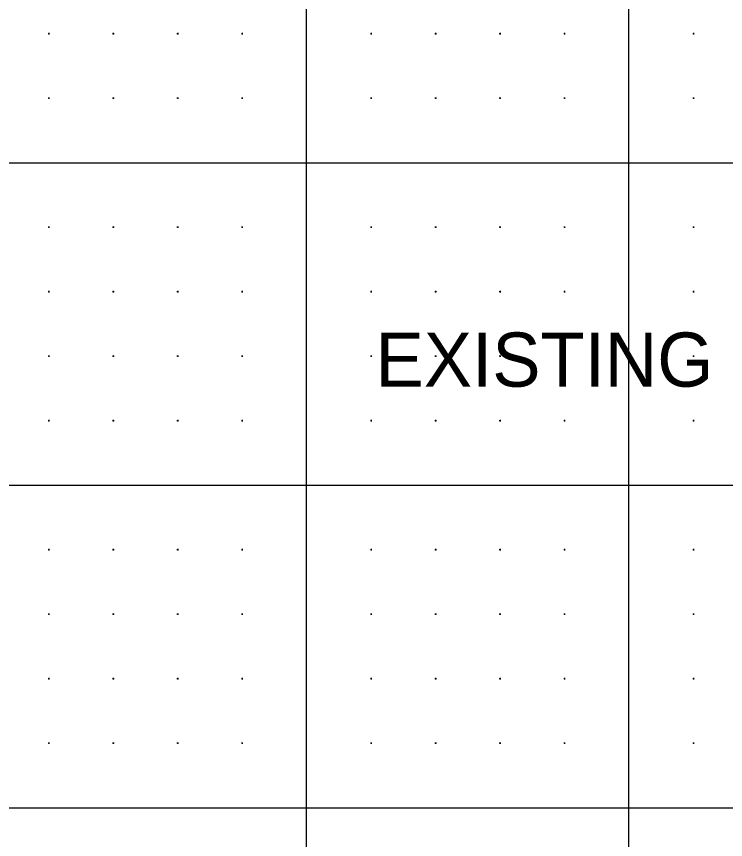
# Model space of a CAD drawing. Extents: x 471 to 2121, y 140 to 650.
# Drawn here: x 691 to 801, y 395.1 to 522.7 of the extents above; entities that cross this region are included whole.
import ezdxf

# ---------------------------------------------------------------- set-up
doc = ezdxf.new("R2010")
doc.units = 0
doc.layers.add('Default', color=7, linetype='Continuous')
doc.layers.add('DSN_DRFT_Border Grid', color=7, linetype='Continuous')

msp = doc.modelspace()

# ---------------------------------------------------------------- linework, layer by layer
at = {"layer": 'DSN_DRFT_Border Grid'}
for p, q in [((736.06, 150), (736.06, 650)), ((736.06, 150), (736.06, 650)), ((786.06, 150), (786.06, 650)), ((786.06, 150), (786.06, 650)), ((696.18, 520), (695.94, 520)), ((696.18, 520), (695.94, 520)), ((696.06, 520.12), (696.06, 519.88)), ((696.06, 520.12), (696.06, 519.88)), ((706.18, 520), (705.94, 520)), ((706.18, 520), (705.94, 520)), ((706.06, 520.12), (706.06, 519.88)), ((706.06, 520.12), (706.06, 519.88)), ((716.18, 520), (715.94, 520)), ((716.18, 520), (715.94, 520)), ((716.06, 520.12), (716.06, 519.88)), ((716.06, 520.12), (716.06, 519.88)), ((726.18, 520), (725.94, 520)), ((726.18, 520), (725.94, 520)), ((726.06, 520.12), (726.06, 519.88)), ((726.06, 520.12), (726.06, 519.88)), ((746.18, 520), (745.94, 520)), ((746.18, 520), (745.94, 520)), ((746.06, 520.12), (746.06, 519.88)), ((746.06, 520.12), (746.06, 519.88)), ((756.18, 520), (755.94, 520)), ((756.18, 520), (755.94, 520)), ((756.06, 520.12), (756.06, 519.88)), ((756.06, 520.12), (756.06, 519.88)), ((766.18, 520), (765.94, 520)), ((766.18, 520), (765.94, 520)), ((766.06, 520.12), (766.06, 519.88)), ((766.06, 520.12), (766.06, 519.88)), ((776.18, 520), (775.94, 520)), ((776.18, 520), (775.94, 520)), ((776.06, 520.12), (776.06, 519.88)), ((776.06, 520.12), (776.06, 519.88)), ((796.18, 520), (795.94, 520)), ((796.18, 520), (795.94, 520)), ((796.06, 520.12), (796.06, 519.88)), ((796.06, 520.12), (796.06, 519.88)), ((696.18, 510), (695.94, 510)), ((696.18, 510), (695.94, 510)), ((696.06, 510.12), (696.06, 509.88)), ((696.06, 510.12), (696.06, 509.88)), ((706.18, 510), (705.94, 510)), ((706.18, 510), (705.94, 510)), ((706.06, 510.12), (706.06, 509.88)), ((706.06, 510.12), (706.06, 509.88)), ((716.18, 510), (715.94, 510)), ((716.18, 510), (715.94, 510)), ((716.06, 510.12), (716.06, 509.88)), ((716.06, 510.12), (716.06, 509.88)), ((726.18, 510), (725.94, 510)), ((726.18, 510), (725.94, 510)), ((726.06, 510.12), (726.06, 509.88)), ((726.06, 510.12), (726.06, 509.88)), ((746.18, 510), (745.94, 510)), ((746.18, 510), (745.94, 510)), ((746.06, 510.12), (746.06, 509.88)), ((746.06, 510.12), (746.06, 509.88)), ((756.18, 510), (755.94, 510)), ((756.18, 510), (755.94, 510)), ((756.06, 510.12), (756.06, 509.88)), ((756.06, 510.12), (756.06, 509.88)), ((766.18, 510), (765.94, 510)), ((766.18, 510), (765.94, 510)), ((766.06, 510.12), (766.06, 509.88)), ((766.06, 510.12), (766.06, 509.88)), ((776.18, 510), (775.94, 510)), ((776.18, 510), (775.94, 510)), ((776.06, 510.12), (776.06, 509.88)), ((776.06, 510.12), (776.06, 509.88)), ((796.18, 510), (795.94, 510)), ((796.18, 510), (795.94, 510)), ((796.06, 510.12), (796.06, 509.88)), ((796.06, 510.12), (796.06, 509.88)), ((521.06, 500), (2071.06, 500)), ((521.06, 500), (2071.06, 500)), ((696.06, 490.12), (696.06, 489.88)), ((696.06, 490.12), (696.06, 489.88)), ((706.06, 490.12), (706.06, 489.88)), ((706.06, 490.12), (706.06, 489.88)), ((716.06, 490.12), (716.06, 489.88)), ((716.06, 490.12), (716.06, 489.88)), ((726.06, 490.12), (726.06, 489.88)), ((726.06, 490.12), (726.06, 489.88)), ((746.06, 490.12), (746.06, 489.88)), ((746.06, 490.12), (746.06, 489.88)), ((756.06, 490.12), (756.06, 489.88)), ((756.06, 490.12), (756.06, 489.88)), ((766.06, 490.12), (766.06, 489.88)), ((766.06, 490.12), (766.06, 489.88)), ((776.06, 490.12), (776.06, 489.88)), ((776.06, 490.12), (776.06, 489.88)), ((796.06, 490.12), (796.06, 489.88)), ((796.06, 490.12), (796.06, 489.88)), ((696.18, 490), (695.94, 490)), ((696.18, 490), (695.94, 490)), ((706.18, 490), (705.94, 490)), ((706.18, 490), (705.94, 490)), ((716.18, 490), (715.94, 490)), ((716.18, 490), (715.94, 490)), ((726.18, 490), (725.94, 490)), ((726.18, 490), (725.94, 490)), ((746.18, 490), (745.94, 490)), ((746.18, 490), (745.94, 490)), ((756.18, 490), (755.94, 490)), ((756.18, 490), (755.94, 490)), ((766.18, 490), (765.94, 490)), ((766.18, 490), (765.94, 490)), ((776.18, 490), (775.94, 490)), ((776.18, 490), (775.94, 490)), ((796.18, 490), (795.94, 490)), ((796.18, 490), (795.94, 490)), ((696.18, 480), (695.94, 480)), ((696.18, 480), (695.94, 480)), ((696.06, 480.12), (696.06, 479.88)), ((696.06, 480.12), (696.06, 479.88)), ((706.18, 480), (705.94, 480)), ((706.18, 480), (705.94, 480)), ((706.06, 480.12), (706.06, 479.88)), ((706.06, 480.12), (706.06, 479.88)), ((716.18, 480), (715.94, 480)), ((716.18, 480), (715.94, 480)), ((716.06, 480.12), (716.06, 479.88)), ((716.06, 480.12), (716.06, 479.88)), ((726.18, 480), (725.94, 480)), ((726.18, 480), (725.94, 480)), ((726.06, 480.12), (726.06, 479.88)), ((726.06, 480.12), (726.06, 479.88)), ((746.18, 480), (745.94, 480)), ((746.18, 480), (745.94, 480)), ((746.06, 480.12), (746.06, 479.88)), ((746.06, 480.12), (746.06, 479.88)), ((756.18, 480), (755.94, 480)), ((756.18, 480), (755.94, 480)), ((756.06, 480.12), (756.06, 479.88)), ((756.06, 480.12), (756.06, 479.88)), ((766.18, 480), (765.94, 480)), ((766.18, 480), (765.94, 480)), ((766.06, 480.12), (766.06, 479.88)), ((766.06, 480.12), (766.06, 479.88)), ((776.18, 480), (775.94, 480)), ((776.18, 480), (775.94, 480)), ((776.06, 480.12), (776.06, 479.88)), ((776.06, 480.12), (776.06, 479.88)), ((796.18, 480), (795.94, 480)), ((796.18, 480), (795.94, 480)), ((796.06, 480.12), (796.06, 479.88)), ((796.06, 480.12), (796.06, 479.88)), ((696.18, 470), (695.94, 470)), ((696.18, 470), (695.94, 470)), ((696.06, 470.12), (696.06, 469.88)), ((696.06, 470.12), (696.06, 469.88)), ((706.18, 470), (705.94, 470)), ((706.18, 470), (705.94, 470)), ((706.06, 470.12), (706.06, 469.88)), ((706.06, 470.12), (706.06, 469.88)), ((716.18, 470), (715.94, 470)), ((716.18, 470), (715.94, 470)), ((716.06, 470.12), (716.06, 469.88)), ((716.06, 470.12), (716.06, 469.88)), ((726.18, 470), (725.94, 470)), ((726.18, 470), (725.94, 470)), ((726.06, 470.12), (726.06, 469.88)), ((726.06, 470.12), (726.06, 469.88)), ((746.18, 470), (745.94, 470)), ((746.18, 470), (745.94, 470)), ((746.06, 470.12), (746.06, 469.88)), ((746.06, 470.12), (746.06, 469.88)), ((756.18, 470), (755.94, 470)), ((756.18, 470), (755.94, 470)), ((756.06, 470.12), (756.06, 469.88)), ((756.06, 470.12), (756.06, 469.88)), ((766.18, 470), (765.94, 470)), ((766.18, 470), (765.94, 470)), ((766.06, 470.12), (766.06, 469.88)), ((766.06, 470.12), (766.06, 469.88)), ((776.18, 470), (775.94, 470)), ((776.18, 470), (775.94, 470)), ((776.06, 470.12), (776.06, 469.88)), ((776.06, 470.12), (776.06, 469.88)), ((796.18, 470), (795.94, 470)), ((796.18, 470), (795.94, 470)), ((796.06, 470.12), (796.06, 469.88)), ((796.06, 470.12), (796.06, 469.88)), ((696.18, 460), (695.94, 460)), ((696.18, 460), (695.94, 460)), ((696.06, 460.12), (696.06, 459.88)), ((696.06, 460.12), (696.06, 459.88)), ((706.18, 460), (705.94, 460)), ((706.18, 460), (705.94, 460)), ((706.06, 460.12), (706.06, 459.88)), ((706.06, 460.12), (706.06, 459.88)), ((716.18, 460), (715.94, 460)), ((716.18, 460), (715.94, 460)), ((716.06, 460.12), (716.06, 459.88)), ((716.06, 460.12), (716.06, 459.88)), ((726.18, 460), (725.94, 460)), ((726.18, 460), (725.94, 460)), ((726.06, 460.12), (726.06, 459.88)), ((726.06, 460.12), (726.06, 459.88)), ((746.18, 460), (745.94, 460)), ((746.18, 460), (745.94, 460)), ((746.06, 460.12), (746.06, 459.88)), ((746.06, 460.12), (746.06, 459.88)), ((756.18, 460), (755.94, 460)), ((756.18, 460), (755.94, 460)), ((756.06, 460.12), (756.06, 459.88)), ((756.06, 460.12), (756.06, 459.88)), ((766.18, 460), (765.94, 460)), ((766.18, 460), (765.94, 460)), ((766.06, 460.12), (766.06, 459.88)), ((766.06, 460.12), (766.06, 459.88)), ((776.18, 460), (775.94, 460)), ((776.18, 460), (775.94, 460)), ((776.06, 460.12), (776.06, 459.88)), ((776.06, 460.12), (776.06, 459.88)), ((796.18, 460), (795.94, 460)), ((796.18, 460), (795.94, 460)), ((796.06, 460.12), (796.06, 459.88)), ((796.06, 460.12), (796.06, 459.88)), ((521.06, 450), (2071.06, 450)), ((521.06, 450), (2071.06, 450)), ((696.18, 440), (695.94, 440)), ((696.18, 440), (695.94, 440)), ((696.06, 440.12), (696.06, 439.88)), ((696.06, 440.12), (696.06, 439.88)), ((706.18, 440), (705.94, 440)), ((706.18, 440), (705.94, 440)), ((706.06, 440.12), (706.06, 439.88)), ((706.06, 440.12), (706.06, 439.88)), ((716.18, 440), (715.94, 440)), ((716.18, 440), (715.94, 440)), ((716.06, 440.12), (716.06, 439.88)), ((716.06, 440.12), (716.06, 439.88)), ((726.18, 440), (725.94, 440)), ((726.18, 440), (725.94, 440)), ((726.06, 440.12), (726.06, 439.88)), ((726.06, 440.12), (726.06, 439.88)), ((746.18, 440), (745.94, 440)), ((746.18, 440), (745.94, 440)), ((746.06, 440.12), (746.06, 439.88)), ((746.06, 440.12), (746.06, 439.88)), ((756.18, 440), (755.94, 440)), ((756.18, 440), (755.94, 440)), ((756.06, 440.12), (756.06, 439.88)), ((756.06, 440.12), (756.06, 439.88)), ((766.18, 440), (765.94, 440)), ((766.18, 440), (765.94, 440)), ((766.06, 440.12), (766.06, 439.88)), ((766.06, 440.12), (766.06, 439.88)), ((776.18, 440), (775.94, 440)), ((776.18, 440), (775.94, 440)), ((776.06, 440.12), (776.06, 439.88)), ((776.06, 440.12), (776.06, 439.88)), ((796.18, 440), (795.94, 440)), ((796.18, 440), (795.94, 440)), ((796.06, 440.12), (796.06, 439.88)), ((796.06, 440.12), (796.06, 439.88)), ((696.06, 430.12), (696.06, 429.88)), ((696.06, 430.12), (696.06, 429.88)), ((706.06, 430.12), (706.06, 429.88)), ((706.06, 430.12), (706.06, 429.88)), ((716.06, 430.12), (716.06, 429.88)), ((716.06, 430.12), (716.06, 429.88)), ((726.06, 430.12), (726.06, 429.88)), ((726.06, 430.12), (726.06, 429.88)), ((746.06, 430.12), (746.06, 429.88)), ((746.06, 430.12), (746.06, 429.88)), ((756.06, 430.12), (756.06, 429.88)), ((756.06, 430.12), (756.06, 429.88)), ((766.06, 430.12), (766.06, 429.88)), ((766.06, 430.12), (766.06, 429.88)), ((776.06, 430.12), (776.06, 429.88)), ((776.06, 430.12), (776.06, 429.88)), ((796.06, 430.12), (796.06, 429.88)), ((796.06, 430.12), (796.06, 429.88)), ((696.18, 430), (695.94, 430)), ((696.18, 430), (695.94, 430)), ((706.18, 430), (705.94, 430)), ((706.18, 430), (705.94, 430)), ((716.18, 430), (715.94, 430)), ((716.18, 430), (715.94, 430)), ((726.18, 430), (725.94, 430)), ((726.18, 430), (725.94, 430)), ((746.18, 430), (745.94, 430)), ((746.18, 430), (745.94, 430)), ((756.18, 430), (755.94, 430)), ((756.18, 430), (755.94, 430)), ((766.18, 430), (765.94, 430)), ((766.18, 430), (765.94, 430)), ((776.18, 430), (775.94, 430)), ((776.18, 430), (775.94, 430)), ((796.18, 430), (795.94, 430)), ((796.18, 430), (795.94, 430)), ((696.18, 420), (695.94, 420)), ((696.18, 420), (695.94, 420)), ((696.06, 420.12), (696.06, 419.88)), ((696.06, 420.12), (696.06, 419.88)), ((706.18, 420), (705.94, 420)), ((706.18, 420), (705.94, 420)), ((706.06, 420.12), (706.06, 419.88)), ((706.06, 420.12), (706.06, 419.88)), ((716.18, 420), (715.94, 420)), ((716.18, 420), (715.94, 420)), ((716.06, 420.12), (716.06, 419.88)), ((716.06, 420.12), (716.06, 419.88)), ((726.18, 420), (725.94, 420)), ((726.18, 420), (725.94, 420)), ((726.06, 420.12), (726.06, 419.88)), ((726.06, 420.12), (726.06, 419.88)), ((746.18, 420), (745.94, 420)), ((746.18, 420), (745.94, 420)), ((746.06, 420.12), (746.06, 419.88)), ((746.06, 420.12), (746.06, 419.88)), ((756.18, 420), (755.94, 420)), ((756.18, 420), (755.94, 420)), ((756.06, 420.12), (756.06, 419.88)), ((756.06, 420.12), (756.06, 419.88)), ((766.18, 420), (765.94, 420)), ((766.18, 420), (765.94, 420)), ((766.06, 420.12), (766.06, 419.88)), ((766.06, 420.12), (766.06, 419.88)), ((776.18, 420), (775.94, 420)), ((776.18, 420), (775.94, 420)), ((776.06, 420.12), (776.06, 419.88)), ((776.06, 420.12), (776.06, 419.88)), ((796.18, 420), (795.94, 420)), ((796.18, 420), (795.94, 420)), ((796.06, 420.12), (796.06, 419.88)), ((796.06, 420.12), (796.06, 419.88)), ((696.18, 410), (695.94, 410)), ((696.18, 410), (695.94, 410)), ((696.06, 410.12), (696.06, 409.88)), ((696.06, 410.12), (696.06, 409.88)), ((706.18, 410), (705.94, 410)), ((706.18, 410), (705.94, 410)), ((706.06, 410.12), (706.06, 409.88)), ((706.06, 410.12), (706.06, 409.88)), ((716.18, 410), (715.94, 410)), ((716.18, 410), (715.94, 410)), ((716.06, 410.12), (716.06, 409.88)), ((716.06, 410.12), (716.06, 409.88)), ((726.18, 410), (725.94, 410)), ((726.18, 410), (725.94, 410)), ((726.06, 410.12), (726.06, 409.88)), ((726.06, 410.12), (726.06, 409.88)), ((746.18, 410), (745.94, 410)), ((746.18, 410), (745.94, 410)), ((746.06, 410.12), (746.06, 409.88)), ((746.06, 410.12), (746.06, 409.88)), ((756.18, 410), (755.94, 410)), ((756.18, 410), (755.94, 410)), ((756.06, 410.12), (756.06, 409.88)), ((756.06, 410.12), (756.06, 409.88)), ((766.18, 410), (765.94, 410)), ((766.18, 410), (765.94, 410)), ((766.06, 410.12), (766.06, 409.88)), ((766.06, 410.12), (766.06, 409.88)), ((776.18, 410), (775.94, 410)), ((776.18, 410), (775.94, 410)), ((776.06, 410.12), (776.06, 409.88)), ((776.06, 410.12), (776.06, 409.88)), ((796.18, 410), (795.94, 410)), ((796.18, 410), (795.94, 410)), ((796.06, 410.12), (796.06, 409.88)), ((796.06, 410.12), (796.06, 409.88)), ((521.06, 400), (2071.06, 400)), ((521.06, 400), (2071.06, 400))]:
    msp.add_line(p, q, dxfattribs=at)

# ---------------------------------------------------------------- texts
at = {"layer": 'Default'}
msp.add_text('EXISTING GROUND', height=8.4, dxfattribs=at).set_placement((746.74, 465.27))

doc.saveas('drawing.dxf')
